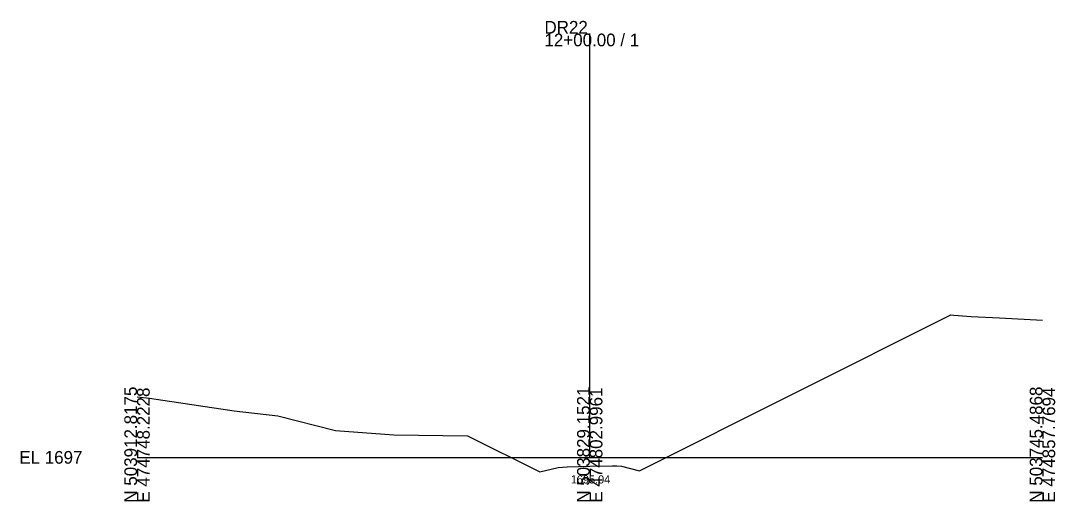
# Model space of a CAD drawing. Extents: x -26 to 1203, y -10 to 9633.
# Drawn here: x -25.7 to 202.8, y 4990.3 to 5096.3 of the extents above; entities that cross this region are included whole.
import ezdxf

# ---------------------------------------------------------------- set-up
doc = ezdxf.new("R2010")
doc.units = 0
for name, color, linetype in [('Exist Cross Section Cell', 7, 'Continuous'), ('Exist XS Center Line Elevation Label', 7, 'Continuous'), ('Exist XS Ground Line', 7, 'Continuous'), ('Scratch_Level_5', 7, 'Continuous')]:
    doc.layers.add(name, color=color, linetype=linetype)

msp = doc.modelspace()

# ---------------------------------------------------------------- linework, layer by layer
at = {"layer": 'Exist Cross Section Cell'}
for p, q in [((100, 5000), (100, 5093.49)), ((0, 5000), (100, 5000)), ((100, 5000), (200, 5000))]:
    msp.add_line(p, q, dxfattribs=at)
at = {"layer": 'Exist XS Ground Line'}
msp.add_lwpolyline([(0, 5013.38), (2.77, 5013.04), (21.46, 5010.23), (31.13, 5009.13), (43.86, 5005.94), (56.71, 5004.94), (73.01, 5004.77), (89, 4996.78), (93, 4997.78), (93.98, 4997.86), (95, 4997.94), (100, 4998.04), (105, 4998.14), (106.02, 4998.1), (107, 4998.06), (111, 4997.06), (179.76, 5031.44), (180.43, 5031.39), (184.22, 5031.11), (190.5, 5030.8), (200, 5030.23)], dxfattribs=at)
at = {"layer": 'Scratch_Level_5'}
msp.add_lwpolyline([(0, 5013.38), (2.77, 5013.04), (21.46, 5010.23), (31.13, 5009.13), (43.86, 5005.94), (56.71, 5004.94), (73.01, 5004.77), (89, 4996.78), (93, 4997.78), (93.98, 4997.86), (95, 4997.94), (100, 4998.04), (105, 4998.14), (106.02, 4998.1), (107, 4998.06), (111, 4997.06), (179.76, 5031.44), (180.43, 5031.39), (184.22, 5031.11), (190.5, 5030.8), (200, 5030.23)], dxfattribs=at)

# ---------------------------------------------------------------- texts
at = {"layer": 'Exist Cross Section Cell'}
for s, p in [('DR22', (90, 5093.49)), ('12+00.00 / 1', (90, 5090.69)), ('EL 1697', (-26, 4998.6))]:
    msp.add_text(s, height=2.8, dxfattribs=at).set_placement(p)
for s, p in [('N 503912.8175', (0, 4990)), ('E 474748.2228', (2.8, 4990)), ('N 503829.1521', (100, 4990)), ('E 474802.9961', (102.8, 4990)), ('N 503745.4868', (200, 4990)), ('E 474857.7694', (202.8, 4990))]:
    msp.add_text(s, height=2.8, rotation=90, dxfattribs=at).set_placement(p)
at = {"layer": 'Exist XS Center Line Elevation Label'}
msp.add_text('1695.04', height=1.8, dxfattribs=at).set_placement((95.82, 4994.24))

doc.saveas('drawing.dxf')
